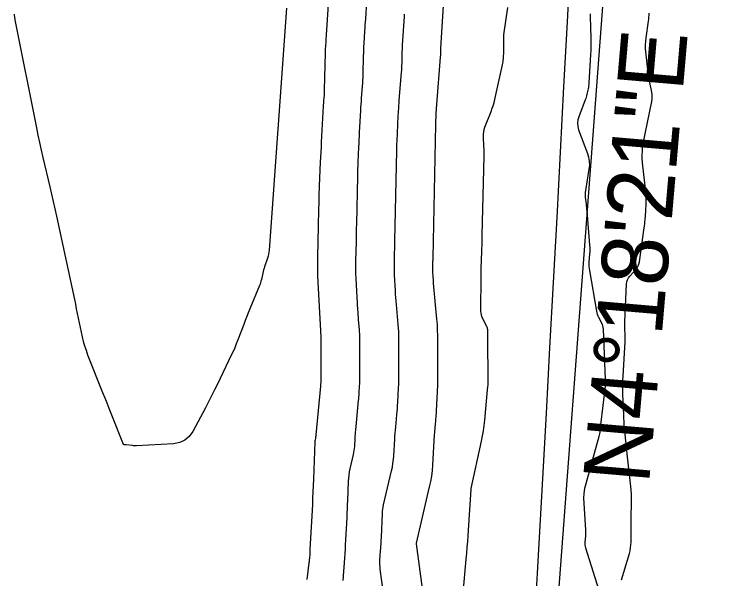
# Model space of a CAD drawing. Extents: x 1768942 to 1774819, y 723037 to 732099.
# Drawn here: x 1770523 to 1770588, y 730822.1 to 730873.2 of the extents above; entities that cross this region are included whole.
import ezdxf

# ---------------------------------------------------------------- set-up
doc = ezdxf.new("R2010")
doc.units = 0
for name, color, linetype in [('R_Contours', 7, 'Continuous'), ('R_Horz Alg', 7, 'Continuous'), ('R_Horz Alg Annot', 7, 'Continuous')]:
    doc.layers.add(name, color=color, linetype=linetype)

msp = doc.modelspace()

# ---------------------------------------------------------------- linework, layer by layer
at = {"layer": 'R_Contours'}
for points in [[(1770551.398, 730874.033), (1770551.225, 730871.295), (1770551.217, 730871.16), (1770551.208, 730871.025), (1770551.2, 730870.891), (1770551.192, 730870.756), (1770551.158, 730870.217), (1770551.151, 730870.082), (1770551.144, 730869.948), (1770551.139, 730869.813), (1770551.136, 730869.678), (1770551.063, 730866.331), (1770551.059, 730866.208), (1770551.054, 730866.085), (1770551.047, 730865.962), (1770551.038, 730865.839), (1770550.998, 730865.348), (1770550.989, 730865.225), (1770550.98, 730865.102), (1770550.972, 730864.979), (1770550.965, 730864.856), (1770550.789, 730861.598), (1770550.764, 730861.141), (1770550.741, 730860.684), (1770550.718, 730860.227), (1770550.697, 730859.769), (1770550.598, 730857.634), (1770550.584, 730857.33), (1770550.573, 730857.025), (1770550.564, 730856.721), (1770550.557, 730856.416), (1770550.532, 730855.197), (1770550.526, 730854.892), (1770550.519, 730854.587), (1770550.512, 730854.282), (1770550.505, 730853.978), (1770550.438, 730851.185), (1770550.43, 730850.618), (1770550.433, 730850.051), (1770550.447, 730849.485), (1770550.472, 730848.918), (1770550.711, 730844.499), (1770550.714, 730844.454), (1770550.717, 730844.409), (1770550.72, 730844.363), (1770550.724, 730844.318), (1770550.741, 730844.125), (1770550.745, 730844.086), (1770550.747, 730844.046), (1770550.748, 730844.007), (1770550.749, 730843.967), (1770550.749, 730843.809), (1770550.749, 730843.769), (1770550.749, 730843.729), (1770550.749, 730843.69), (1770550.749, 730843.65), (1770550.74, 730839.996), (1770550.74, 730839.955), (1770550.739, 730839.914), (1770550.738, 730839.873), (1770550.736, 730839.832), (1770550.727, 730839.668), (1770550.724, 730839.627), (1770550.721, 730839.586), (1770550.718, 730839.545), (1770550.714, 730839.504), (1770550.288, 730835.075), (1770550.285, 730835.051), (1770550.283, 730835.027), (1770550.282, 730835.002), (1770550.28, 730834.978), (1770550.274, 730834.881), (1770550.272, 730834.856), (1770550.269, 730834.832), (1770550.265, 730834.808), (1770550.26, 730834.784), (1770550.22, 730834.611), (1770550.212, 730834.574), (1770550.206, 730834.537), (1770550.202, 730834.5), (1770550.2, 730834.462), (1770550.079, 730831.085), (1770550.057, 730830.51), (1770550.033, 730829.934), (1770550.006, 730829.359), (1770549.977, 730828.784), (1770549.762, 730824.714), (1770549.757, 730824.611), (1770549.751, 730824.509), (1770549.744, 730824.407), (1770549.737, 730824.304), (1770549.708, 730823.895), (1770549.7, 730823.793), (1770549.691, 730823.691), (1770549.68, 730823.589), (1770549.667, 730823.488), (1770549.465, 730821.995)], [(1770552.77, 730821.895), (1770552.913, 730823.931), (1770552.941, 730824.341), (1770552.967, 730824.75), (1770552.991, 730825.16), (1770553.014, 730825.57), (1770553.121, 730827.606), (1770553.141, 730827.99), (1770553.158, 730828.375), (1770553.175, 730828.759), (1770553.189, 730829.143), (1770553.251, 730830.88), (1770553.268, 730831.164), (1770553.299, 730831.446), (1770553.344, 730831.727), (1770553.402, 730832.005), (1770553.707, 730833.312), (1770553.745, 730833.491), (1770553.776, 730833.672), (1770553.798, 730833.854), (1770553.813, 730834.038), (1770553.857, 730834.773), (1770553.869, 730834.956), (1770553.882, 730835.14), (1770553.898, 730835.323), (1770553.914, 730835.506), (1770554.173, 730838.187), (1770554.188, 730838.355), (1770554.202, 730838.524), (1770554.213, 730838.693), (1770554.224, 730838.862), (1770554.261, 730839.538), (1770554.269, 730839.707), (1770554.275, 730839.876), (1770554.279, 730840.045), (1770554.28, 730840.215), (1770554.285, 730842.322), (1770554.286, 730842.512), (1770554.286, 730842.702), (1770554.286, 730842.893), (1770554.285, 730843.083), (1770554.283, 730843.844), (1770554.281, 730844.034), (1770554.274, 730844.224), (1770554.263, 730844.413), (1770554.248, 730844.603), (1770554.164, 730845.527), (1770554.146, 730845.744), (1770554.129, 730845.962), (1770554.114, 730846.179), (1770554.102, 730846.397), (1770553.948, 730849.238), (1770553.93, 730849.65), (1770553.92, 730850.062), (1770553.918, 730850.473), (1770553.923, 730850.885), (1770553.963, 730852.533), (1770553.973, 730852.945), (1770553.982, 730853.357), (1770553.991, 730853.769), (1770553.999, 730854.181), (1770554.086, 730858.47), (1770554.094, 730858.802), (1770554.104, 730859.134), (1770554.116, 730859.466), (1770554.131, 730859.798), (1770554.192, 730861.126), (1770554.208, 730861.458), (1770554.224, 730861.79), (1770554.241, 730862.122), (1770554.259, 730862.453), (1770554.367, 730864.445), (1770554.383, 730864.72), (1770554.4, 730864.996), (1770554.42, 730865.272), (1770554.441, 730865.547), (1770554.53, 730866.648), (1770554.55, 730866.924), (1770554.566, 730867.199), (1770554.578, 730867.475), (1770554.586, 730867.751), (1770554.622, 730869.395), (1770554.629, 730869.676), (1770554.64, 730869.956), (1770554.653, 730870.236), (1770554.669, 730870.516), (1770554.738, 730871.636), (1770554.755, 730871.916), (1770554.773, 730872.196), (1770554.79, 730872.476), (1770554.808, 730872.756), (1770554.907, 730874.319)], [(1770559.953, 730821.188), (1770559.408, 730825.207), (1770559.408, 730825.212), (1770559.408, 730825.217), (1770559.409, 730825.238), (1770559.41, 730825.26), (1770559.411, 730825.272), (1770559.412, 730825.279), (1770560.602, 730830.366), (1770560.706, 730830.858), (1770560.789, 730831.353), (1770560.85, 730831.851), (1770560.891, 730832.352), (1770561.056, 730835.108), (1770561.064, 730835.237), (1770561.074, 730835.366), (1770561.084, 730835.496), (1770561.096, 730835.625), (1770561.146, 730836.141), (1770561.158, 730836.27), (1770561.168, 730836.4), (1770561.177, 730836.529), (1770561.185, 730836.658), (1770561.346, 730839.589), (1770561.351, 730839.695), (1770561.355, 730839.801), (1770561.357, 730839.907), (1770561.358, 730840.013), (1770561.359, 730840.436), (1770561.359, 730840.542), (1770561.359, 730840.648), (1770561.359, 730840.754), (1770561.359, 730840.86), (1770561.352, 730843.596), (1770561.345, 730844.087), (1770561.328, 730844.578), (1770561.3, 730845.068), (1770561.261, 730845.557), (1770560.966, 730848.814), (1770560.956, 730848.94), (1770560.946, 730849.067), (1770560.937, 730849.194), (1770560.93, 730849.321), (1770560.9, 730849.878), (1770560.895, 730849.98), (1770560.893, 730850.082), (1770560.892, 730850.184), (1770560.894, 730850.286), (1770560.903, 730850.694), (1770560.906, 730850.796), (1770560.908, 730850.898), (1770560.91, 730851), (1770560.912, 730851.102), (1770561.158, 730863.189), (1770561.159, 730863.27), (1770561.162, 730863.352), (1770561.165, 730863.433), (1770561.168, 730863.514), (1770561.183, 730863.839), (1770561.187, 730863.92), (1770561.191, 730864.001), (1770561.195, 730864.082), (1770561.2, 730864.163), (1770561.223, 730864.589), (1770561.228, 730864.687), (1770561.235, 730864.785), (1770561.242, 730864.883), (1770561.249, 730864.981), (1770561.596, 730869.29), (1770561.601, 730869.358), (1770561.605, 730869.426), (1770561.608, 730869.495), (1770561.61, 730869.563), (1770561.616, 730869.836), (1770561.617, 730869.904), (1770561.62, 730869.973), (1770561.623, 730870.041), (1770561.627, 730870.109), (1770561.894, 730874.421)], [(1770547.631, 730873.707), (1770546.068, 730851.796), (1770546.049, 730851.613), (1770546.018, 730851.431), (1770545.975, 730851.253), (1770545.921, 730851.076), (1770545.654, 730850.306), (1770545.607, 730850.165), (1770545.565, 730850.023), (1770545.526, 730849.88), (1770545.492, 730849.736), (1770545.361, 730849.157), (1770545.326, 730849.013), (1770545.284, 730848.871), (1770545.237, 730848.731), (1770545.183, 730848.593), (1770544.318, 730846.492), (1770544.176, 730846.142), (1770544.036, 730845.792), (1770543.899, 730845.44), (1770543.764, 730845.087), (1770543.229, 730843.675), (1770543.092, 730843.324), (1770542.947, 730842.975), (1770542.794, 730842.63), (1770542.634, 730842.289), (1770541.379, 730839.69), (1770541.115, 730839.149), (1770540.845, 730838.611), (1770540.57, 730838.075), (1770540.289, 730837.542), (1770539.146, 730835.394), (1770538.83, 730834.934), (1770538.435, 730834.596), (1770537.963, 730834.38), (1770537.412, 730834.286), (1770534.059, 730834.096), (1770533.967, 730834.093), (1770533.876, 730834.095), (1770533.785, 730834.1), (1770533.694, 730834.11), (1770533.115, 730834.188), (1770533.109, 730834.188), (1770533.104, 730834.189), (1770533.098, 730834.189), (1770533.093, 730834.189), (1770532.953, 730834.18), (1770532.93, 730834.182), (1770532.911, 730834.19), (1770532.895, 730834.204), (1770532.884, 730834.224), (1770531.764, 730837.005), (1770531.574, 730837.476), (1770531.386, 730837.948), (1770531.198, 730838.419), (1770531.01, 730838.892), (1770529.656, 730842.311), (1770529.506, 730842.716), (1770529.373, 730843.126), (1770529.258, 730843.542), (1770529.161, 730843.963), (1770528.808, 730845.658), (1770528.72, 730846.082), (1770528.63, 730846.505), (1770528.541, 730846.929), (1770528.45, 730847.352), (1770526.834, 730854.884), (1770526.688, 730855.552), (1770526.539, 730856.219), (1770526.386, 730856.884), (1770526.229, 730857.55), (1770525.593, 730860.208), (1770525.438, 730860.873), (1770525.288, 730861.54), (1770525.146, 730862.208), (1770525.009, 730862.878), (1770523.069, 730872.645), (1770523.058, 730872.699), (1770523.049, 730872.753), (1770523.04, 730872.807), (1770523.032, 730872.861), (1770523.002, 730873.078), (1770522.994, 730873.132), (1770522.987, 730873.186)], [(1770563.632, 730820.761), (1770563.92, 730823.831), (1770563.968, 730824.367), (1770564.012, 730824.904), (1770564.052, 730825.441), (1770564.088, 730825.978), (1770564.35, 730830.18), (1770564.351, 730830.186), (1770564.352, 730830.203), (1770564.353, 730830.21), (1770564.354, 730830.216), (1770565.303, 730834.524), (1770565.398, 730834.993), (1770565.479, 730835.465), (1770565.545, 730835.939), (1770565.596, 730836.415), (1770565.845, 730839.163), (1770565.85, 730839.222), (1770565.856, 730839.281), (1770565.862, 730839.339), (1770565.869, 730839.398), (1770565.895, 730839.631), (1770565.901, 730839.69), (1770565.905, 730839.748), (1770565.908, 730839.807), (1770565.908, 730839.866), (1770565.883, 730843.993), (1770565.883, 730844.07), (1770565.881, 730844.146), (1770565.879, 730844.223), (1770565.876, 730844.299), (1770565.864, 730844.606), (1770565.857, 730844.681), (1770565.842, 730844.754), (1770565.818, 730844.826), (1770565.787, 730844.895), (1770565.399, 730845.647), (1770565.332, 730845.797), (1770565.285, 730845.952), (1770565.257, 730846.112), (1770565.248, 730846.276), (1770565.261, 730849.431), (1770565.264, 730849.743), (1770565.269, 730850.056), (1770565.278, 730850.368), (1770565.288, 730850.68), (1770565.337, 730851.929), (1770565.348, 730852.242), (1770565.358, 730852.554), (1770565.367, 730852.866), (1770565.375, 730853.179), (1770565.533, 730860.317), (1770565.536, 730860.538), (1770565.535, 730860.758), (1770565.53, 730860.979), (1770565.521, 730861.199), (1770565.477, 730862.081), (1770565.478, 730862.3), (1770565.501, 730862.515), (1770565.547, 730862.726), (1770565.615, 730862.934), (1770566.166, 730864.353), (1770566.279, 730864.66), (1770566.379, 730864.97), (1770566.468, 730865.285), (1770566.544, 730865.602), (1770567.2, 730868.577), (1770567.229, 730868.724), (1770567.253, 730868.872), (1770567.27, 730869.02), (1770567.282, 730869.17), (1770567.322, 730869.82), (1770567.328, 730869.944), (1770567.331, 730870.068), (1770567.331, 730870.192), (1770567.328, 730870.316), (1770567.311, 730870.813), (1770567.309, 730870.937), (1770567.313, 730871.061), (1770567.322, 730871.184), (1770567.336, 730871.308), (1770567.676, 730873.775)], [(1770556.426, 730820.744), (1770556.129, 730822.934), (1770556.107, 730823.138), (1770556.095, 730823.344), (1770556.093, 730823.549), (1770556.103, 730823.755), (1770556.161, 730824.579), (1770556.175, 730824.785), (1770556.188, 730824.991), (1770556.2, 730825.198), (1770556.211, 730825.404), (1770556.265, 730826.428), (1770556.275, 730826.622), (1770556.284, 730826.815), (1770556.292, 730827.008), (1770556.3, 730827.202), (1770556.327, 730827.975), (1770556.339, 730828.168), (1770556.36, 730828.36), (1770556.39, 730828.55), (1770556.429, 730828.739), (1770557.155, 730831.839), (1770557.226, 730832.175), (1770557.282, 730832.513), (1770557.324, 730832.852), (1770557.352, 730833.195), (1770557.442, 730834.7), (1770557.46, 730834.976), (1770557.48, 730835.253), (1770557.503, 730835.529), (1770557.528, 730835.805), (1770557.635, 730836.909), (1770557.66, 730837.186), (1770557.682, 730837.462), (1770557.702, 730837.738), (1770557.718, 730838.015), (1770557.793, 730839.38), (1770557.804, 730839.609), (1770557.813, 730839.839), (1770557.818, 730840.068), (1770557.82, 730840.298), (1770557.822, 730841.216), (1770557.822, 730841.446), (1770557.822, 730841.675), (1770557.822, 730841.905), (1770557.822, 730842.135), (1770557.817, 730843.72), (1770557.813, 730844.06), (1770557.801, 730844.401), (1770557.781, 730844.74), (1770557.754, 730845.08), (1770557.592, 730846.876), (1770557.565, 730847.195), (1770557.54, 730847.515), (1770557.519, 730847.834), (1770557.5, 730848.153), (1770557.424, 730849.558), (1770557.413, 730849.815), (1770557.406, 730850.072), (1770557.405, 730850.329), (1770557.409, 730850.586), (1770557.433, 730851.614), (1770557.439, 730851.871), (1770557.445, 730852.128), (1770557.451, 730852.385), (1770557.456, 730852.642), (1770557.622, 730860.829), (1770557.627, 730861.036), (1770557.633, 730861.243), (1770557.641, 730861.449), (1770557.649, 730861.656), (1770557.688, 730862.482), (1770557.698, 730862.689), (1770557.708, 730862.895), (1770557.718, 730863.102), (1770557.729, 730863.308), (1770557.788, 730864.392), (1770557.802, 730864.641), (1770557.818, 730864.891), (1770557.836, 730865.14), (1770557.855, 730865.389), (1770558.057, 730867.901), (1770558.072, 730868.107), (1770558.084, 730868.313), (1770558.093, 730868.519), (1770558.099, 730868.725), (1770558.117, 730869.551), (1770558.123, 730869.758), (1770558.13, 730869.964), (1770558.14, 730870.17), (1770558.152, 730870.377), (1770558.312, 730872.959), (1770558.324, 730873.163)], [(1770575.138, 730873.206), (1770575.135, 730873.089), (1770575.136, 730872.972), (1770575.204, 730870.988), (1770575.213, 730870.618), (1770575.212, 730870.249), (1770575.203, 730869.88), (1770575.185, 730869.51), (1770575.031, 730866.943), (1770575.02, 730866.813), (1770575.005, 730866.683), (1770574.984, 730866.555), (1770574.959, 730866.427), (1770574.846, 730865.917), (1770574.816, 730865.79), (1770574.78, 730865.664), (1770574.74, 730865.54), (1770574.695, 730865.418), (1770574.102, 730863.889), (1770574.015, 730863.593), (1770573.985, 730863.298), (1770574.011, 730863.001), (1770574.094, 730862.705), (1770574.894, 730860.568), (1770575.002, 730860.215), (1770575.06, 730859.858), (1770575.071, 730859.496), (1770575.033, 730859.129), (1770574.712, 730857.222), (1770574.692, 730857.068), (1770574.683, 730856.913), (1770574.685, 730856.759), (1770574.698, 730856.604), (1770574.773, 730855.984), (1770574.791, 730855.829), (1770574.807, 730855.674), (1770574.822, 730855.519), (1770574.835, 730855.363), (1770575.09, 730852.249), (1770575.102, 730852.057), (1770575.106, 730851.866), (1770575.103, 730851.675), (1770575.093, 730851.483), (1770575.037, 730850.717), (1770575.029, 730850.526), (1770575.032, 730850.336), (1770575.048, 730850.146), (1770575.074, 730849.956), (1770575.71, 730846.289), (1770575.741, 730846.146), (1770575.781, 730846.006), (1770575.833, 730845.87), (1770575.895, 730845.738), (1770576.165, 730845.215), (1770576.224, 730845.083), (1770576.269, 730844.946), (1770576.298, 730844.805), (1770576.311, 730844.66), (1770576.497, 730840.102), (1770576.498, 730840.052), (1770576.5, 730840.003), (1770576.501, 730839.953), (1770576.501, 730839.903), (1770576.502, 730839.705), (1770576.502, 730839.655), (1770576.5, 730839.606), (1770576.497, 730839.556), (1770576.492, 730839.507), (1770576.093, 730835.995), (1770576.086, 730835.936), (1770576.08, 730835.878), (1770576.074, 730835.82), (1770576.069, 730835.761), (1770576.048, 730835.528), (1770576.041, 730835.469), (1770576.033, 730835.411), (1770576.024, 730835.354), (1770576.012, 730835.296), (1770575.93, 730834.926), (1770575.912, 730834.846), (1770575.893, 730834.765), (1770575.872, 730834.685), (1770575.85, 730834.606), (1770574.741, 730830.664), (1770574.638, 730830.227), (1770574.573, 730829.786), (1770574.547, 730829.342), (1770574.559, 730828.893), (1770574.725, 730826.463), (1770574.731, 730826.327), (1770574.732, 730826.191), (1770574.728, 730826.055), (1770574.717, 730825.919), (1770574.664, 730825.377), (1770574.658, 730825.242), (1770574.665, 730825.108), (1770574.686, 730824.976), (1770574.72, 730824.845), (1770576.08, 730820.558)], [(1770577.968, 730821.948), (1770578.694, 730824.338), (1770578.762, 730824.595), (1770578.811, 730824.854), (1770578.841, 730825.116), (1770578.852, 730825.381), (1770578.858, 730826.446), (1770578.86, 730826.713), (1770578.862, 730826.979), (1770578.866, 730827.245), (1770578.87, 730827.512), (1770578.896, 730829.049), (1770578.897, 730829.394), (1770578.886, 730829.738), (1770578.864, 730830.082), (1770578.831, 730830.425), (1770578.498, 730833.382), (1770578.466, 730833.674), (1770578.435, 730833.967), (1770578.404, 730834.259), (1770578.375, 730834.552), (1770578.26, 730835.724), (1770578.233, 730836.017), (1770578.211, 730836.31), (1770578.193, 730836.603), (1770578.179, 730836.897), (1770578.108, 730838.759), (1770578.098, 730839.167), (1770578.097, 730839.575), (1770578.106, 730839.983), (1770578.126, 730840.391), (1770578.311, 730843.504), (1770578.318, 730843.655), (1770578.322, 730843.806), (1770578.322, 730843.958), (1770578.318, 730844.109), (1770578.295, 730844.714), (1770578.291, 730844.866), (1770578.29, 730845.017), (1770578.292, 730845.168), (1770578.297, 730845.32), (1770578.437, 730848.76), (1770578.462, 730848.954), (1770578.518, 730849.136), (1770578.606, 730849.304), (1770578.726, 730849.459), (1770579.27, 730850.052), (1770579.393, 730850.207), (1770579.488, 730850.374), (1770579.557, 730850.554), (1770579.599, 730850.747), (1770580.037, 730853.818), (1770580.061, 730853.998), (1770580.083, 730854.178), (1770580.101, 730854.358), (1770580.116, 730854.539), (1770580.178, 730855.334), (1770580.188, 730855.48), (1770580.197, 730855.625), (1770580.203, 730855.771), (1770580.208, 730855.916), (1770580.224, 730856.499), (1770580.225, 730856.645), (1770580.221, 730856.79), (1770580.212, 730856.935), (1770580.198, 730857.08), (1770579.89, 730859.712), (1770579.875, 730859.858), (1770579.866, 730860.005), (1770579.861, 730860.152), (1770579.861, 730860.299), (1770579.872, 730860.888), (1770579.878, 730861.035), (1770579.891, 730861.181), (1770579.911, 730861.326), (1770579.938, 730861.471), (1770580.728, 730865.252), (1770580.762, 730865.468), (1770580.773, 730865.685), (1770580.762, 730865.901), (1770580.728, 730866.117), (1770580.548, 730866.983), (1770580.506, 730867.199), (1770580.468, 730867.417), (1770580.436, 730867.635), (1770580.408, 730867.854), (1770580.19, 730869.769), (1770580.164, 730870.083), (1770580.159, 730870.397), (1770580.173, 730870.711), (1770580.207, 730871.024), (1770580.422, 730872.548), (1770580.444, 730872.726), (1770580.461, 730872.905), (1770580.472, 730873.084), (1770580.478, 730873.264)]]:
    msp.add_lwpolyline(points, dxfattribs=at)
at = {"layer": 'R_Horz Alg'}
msp.add_line((1770556.177, 730606.87), (1770584.608, 730984.478), dxfattribs=at)
msp.add_arc((1759129.36, 731467.219), 11459.16, 355.6942048, 359.4795914, dxfattribs=at)

# ---------------------------------------------------------------- texts
at = {"layer": 'R_Horz Alg Annot'}
msp.add_text('N4%%d18\'21"E', height=6, rotation=85.08386, dxfattribs=at).set_placement((1770580.469, 730830.546))

doc.saveas('drawing.dxf')
